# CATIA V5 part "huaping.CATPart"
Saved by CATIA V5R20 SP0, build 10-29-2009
Part number: 花瓶
Material "无"
Material "Bordeaux Red": density 7860 kg/m3, Young's modulus 2e+11 Pa, Poisson ratio 0.266
Material "Smoked Glass": density 2190 kg/m3, Young's modulus 6.5e+10 Pa, Poisson ratio 0.161, thermal expansion 8e-05 1/K
Bounding box of the stored display mesh (mm): x -40 to 40, y -40 to 45.921, z -0.446 to 139.494
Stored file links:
  I:\CATIA\huaping.CATPart
  G:\catia v20\win_b64\startup\materials\Catalog.CATMaterial
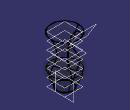
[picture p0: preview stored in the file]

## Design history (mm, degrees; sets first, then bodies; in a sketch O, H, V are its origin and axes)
Set1, material "Bordeaux Red"
  Plane1: type Offset, RefPlane xy-plane, Offset 20
  Plane2: type Offset, RefPlane Plane1, Offset 20
  Plane3: type Offset, RefPlane Plane2, Offset 20
  Plane4: type Offset, RefPlane Plane3, Offset 20
  Plane5: type Offset, RefPlane Plane4, Offset 20
  Plane6: type Offset, RefPlane Plane5, Offset 20
  Sketch1 on Plane2, origin (0, 0, 40), H (1, 0, 0), V (0, 1, 0)
    circle A1 centre (0, 0) radius 40
    radius A1 = 40
  Sketch2 on xy-plane, origin (0, 0, 0), H (1, 0, 0), V (0, 1, 0)
    circle A1 centre (0, 0) radius 20
    radius A1 = 20
  Sketch3 on Plane1, origin (0, 0, 20), H (1, 0, 0), V (0, 1, 0)
    circle A1 centre (0, 0) radius 30
    radius A1 = 30
  Sketch4 on Plane3, origin (0, 0, 60), H (1, 0, 0), V (0, 1, 0)
    circle A1 centre (0, 0) radius 30
    point P1 (30, 0)
    distance P1 V = 30
    radius A1 = 30
    coincidence: A1 P1
  Sketch5 on Plane4, origin (0, 0, 80), H (1, 0, 0), V (0, 1, 0)
    circle A1 centre (0, 0) radius 20
    radius A1 = 20
  Sketch6 on Plane5, origin (0, 0, 100), H (1, 0, 0), V (0, 1, 0)
    circle A1 centre (0, 0) radius 25
    radius A1 = 25
  Sketch7 on Plane6, origin (0, 0, 120), H (1, 0, 0), V (0, 1, 0)
    circle A1 centre (0, 0) radius 35
    radius A1 = 35
Body1 (main body), material "Smoked Glass"
  Loft1: solid, Sections (Sketch2; Sketch3; Sketch1; Sketch4; Sketch5; Sketch6; Sketch7)
  Shell1: IntOffset 1, Face face of Loft1, ExtOffset 0
  Sketch8 on yz-plane, origin (0, 0, 0), H (0, 1, 0), V (0, 0, 1)
    spline S1 through (0, 0) (9.2169, 27.8774) (10.5995, 97.4849) (40.5555, 137.9169) (45.3945, 135.6197)
    point P1 (0, 0)
    coincidence: P1 O
  Plane7: type Normal, Curve Sketch8
  Plane8: type Normal, Curve Sketch8, RefPoint vertex of Sketch8
  Sketch9 on yz-plane, origin (0, 0, 0), H (0, 1, 0), V (0, 0, 1)
    spline S1 through (0, 40.1874) (34.2885, 40.1874)
    spline S2 through (34.2885, 40.1874) (28.6154, 21.0445) (18.3601, 0)
    line L1 (18.3601, 0) -> (0, 0)
    point P1 (18.3601, 0)
    axis line L2 (0, 1.0315) -> (0, 120.2394)
    point P2 (0, 1.0315)
    point P4 (0, 40.1874)
    point P5 (34.2885, 40.1874)
    point P6 (34.2885, 40.1874)
    point P7 (18.3601, 0)
    coincidence: P4 V, P5 P6, P7 H, P7 P1, P2 V
    horizontal: L1 H
    vertical: L2 V
  Shaft1: profile Sketch9, axis Sketch9.L2, angle 360
  Sketch10 on Plane8, origin (0, -28.9381, 18.3413), H (1, 0, 0), V (0, 0.5353, 0.8446)
    circle A1 centre (0, 138.835) radius 1
    point P1 (0, 138.835)
    radius A1 = 1
    coincidence: P1 V
  Rib1: profile Sketch10, centre curve Sketch8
